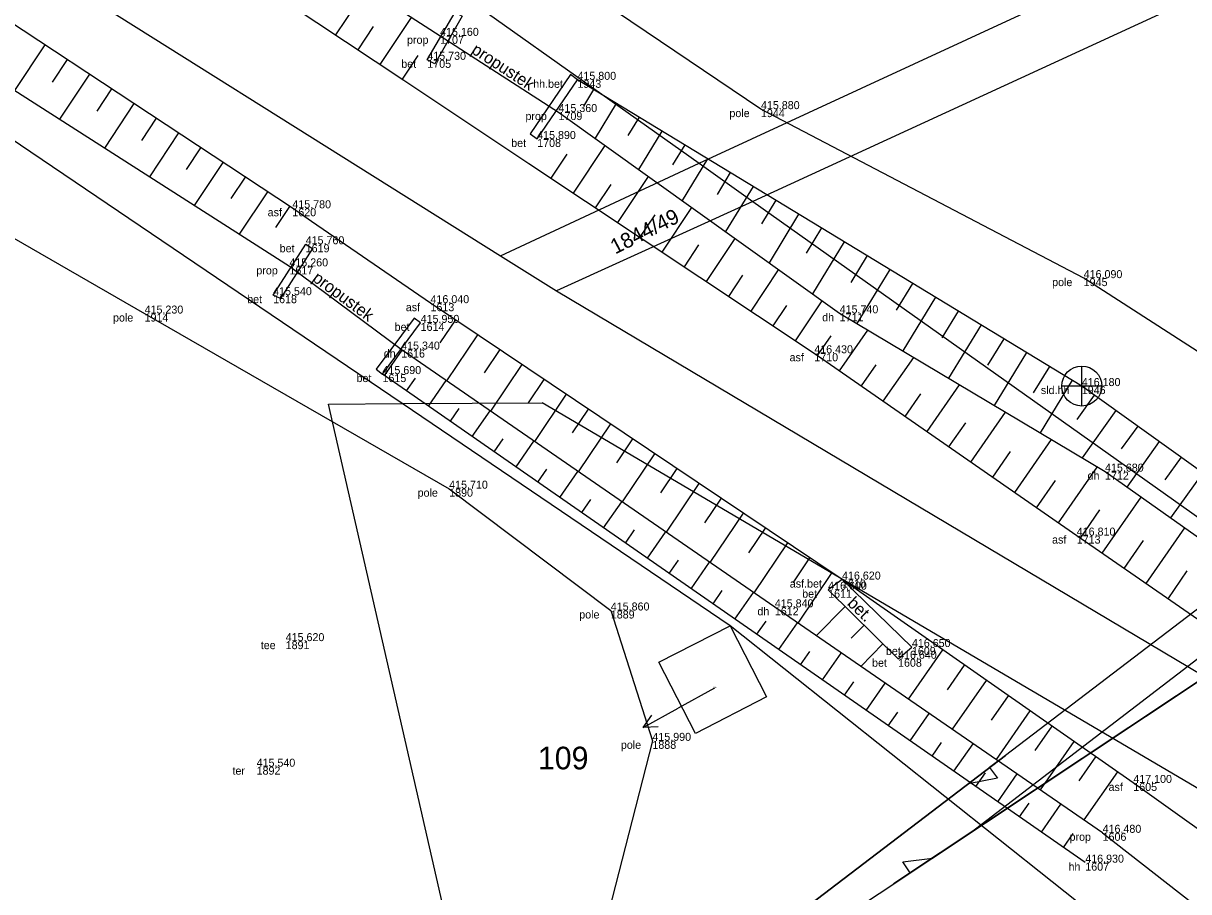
# Model space of a CAD drawing. Extents: x -747792 to -745414, y -1093712 to -1091463.
# Drawn here: x -746827.19 to -746783.49, y -1092384.49 to -1092351.91 of the extents above; entities that cross this region are included whole.
import ezdxf

# ---------------------------------------------------------------- set-up
doc = ezdxf.new("R2010")
doc.units = 0
for name, color, linetype in [('Doplňkové značky', 7, 'Continuous'), ('Hladina', 7, 'Continuous'), ('Koleje_dopravní prvky', 7, 'Continuous'), ('Nivelační značky_hrany', 7, 'Continuous'), ('Pracovní_bod JDTM STC_VC - výška', 7, 'Continuous'), ('Pracovní_bod PPBP', 7, 'Continuous'), ('Pracovní_bod ZPBP', 7, 'Continuous'), ('Pracovní_bod ZPBP - číslo', 7, 'Continuous'), ('Rozhraní ploch', 7, 'Continuous'), ('Stromy_porost', 7, 'Continuous'), ('Výškopis', 7, 'Continuous'), ('Značky IS', 7, 'Continuous'), ('Čísla popisná_parcelní', 7, 'Continuous')]:
    doc.layers.add(name, color=color, linetype=linetype)

msp = doc.modelspace()

# ---------------------------------------------------------------- linework, layer by layer
at = {"layer": 'Doplňkové značky'}
for points in [[(-746801.27, -1092376.85), (-746802.63, -1092377.6)], [(-746803.944, -1092378.324), (-746802.63, -1092377.6)], [(-746803.385, -1092378.302), (-746803.944, -1092378.324), (-746803.626, -1092377.864)]]:
    msp.add_lwpolyline(points, dxfattribs=at)
at = {"layer": 'Hladina'}
for p, q in [((-746811.56, -1092352.38), (-746811.56, -1092352.38)), ((-746812.04, -1092353.28), (-746812.04, -1092353.28)), ((-746806.41, -1092354.03), (-746806.41, -1092354.03)), ((-746807.12, -1092355.24), (-746807.12, -1092355.24)), ((-746799.53, -1092355.13), (-746799.53, -1092355.13)), ((-746807.92, -1092356.25), (-746807.92, -1092356.25)), ((-746817.1, -1092358.85), (-746817.1, -1092358.85)), ((-746816.6, -1092360.2), (-746816.6, -1092360.2)), ((-746817.21, -1092361.03), (-746817.21, -1092361.03)), ((-746787.43, -1092361.47), (-746787.43, -1092361.47)), ((-746817.82, -1092362.11), (-746817.82, -1092362.11)), ((-746811.92, -1092362.41), (-746811.92, -1092362.41)), ((-746822.64, -1092362.8), (-746822.64, -1092362.8)), ((-746796.58, -1092362.79), (-746796.58, -1092362.79)), ((-746812.29, -1092363.15), (-746812.29, -1092363.15)), ((-746813.02, -1092364.15), (-746813.02, -1092364.15)), ((-746797.53, -1092364.29), (-746797.53, -1092364.29)), ((-746813.72, -1092365.07), (-746813.72, -1092365.07)), ((-746787.5, -1092365.52), (-746787.5, -1092365.52)), ((-746786.63, -1092368.73), (-746786.63, -1092368.73)), ((-746811.22, -1092369.37), (-746811.22, -1092369.37)), ((-746787.69, -1092371.13), (-746787.69, -1092371.13)), ((-746796.49, -1092372.78), (-746796.49, -1092372.78)), ((-746797.01, -1092373.16), (-746797.01, -1092373.16)), ((-746799.01, -1092373.82), (-746799.01, -1092373.82)), ((-746805.16, -1092373.94), (-746805.16, -1092373.94)), ((-746817.35, -1092375.09), (-746817.35, -1092375.09)), ((-746793.87, -1092375.31), (-746793.87, -1092375.31)), ((-746794.39, -1092375.75), (-746794.39, -1092375.75)), ((-746803.6, -1092378.83), (-746803.6, -1092378.83)), ((-746818.44, -1092379.8), (-746818.44, -1092379.8)), ((-746785.57, -1092380.41), (-746785.57, -1092380.41)), ((-746786.72, -1092382.28), (-746786.72, -1092382.28)), ((-746787.37, -1092383.4), (-746787.37, -1092383.4))]:
    msp.add_line(p, q, dxfattribs=at)
at = {"layer": 'Nivelační značky_hrany'}
for points in [[(-746816.378, -1092359.346), (-746817.1, -1092358.85), (-746833.74, -1092347.85), (-746852.12, -1092335.65), (-746868.14, -1092324.85), (-746875.06, -1092319.76), (-746884.36, -1092312.88), (-746888.58, -1092309.74), (-746904.34, -1092297.28), (-746918.62, -1092285.83), (-746930.682, -1092276.083)], [(-746887.66, -1092302.09), (-746880.53, -1092307.62), (-746872.41, -1092313.76), (-746861.83, -1092321.34), (-746850.87, -1092329.15), (-746834.21, -1092340.08), (-746822.74, -1092347.51), (-746812.918, -1092354.047)], [(-746812.04, -1092353.28), (-746810.99, -1092351.49), (-746810.73, -1092351.64), (-746811.762, -1092353.434), (-746812.04, -1092353.28)], [(-746812.916, -1092354.049), (-746808.229, -1092357.169)], [(-746807.92, -1092356.25), (-746806.41, -1092354.03), (-746806.67, -1092353.83), (-746808.188, -1092356.058), (-746807.92, -1092356.25)], [(-746808.227, -1092357.17), (-746797.53, -1092364.29), (-746787.69, -1092371.13), (-746776.62, -1092378.78), (-746765.54, -1092386.79), (-746755.3, -1092394.62), (-746745.57, -1092402.66), (-746737.91, -1092409.79), (-746728.85, -1092419.26), (-746722.7, -1092426.86), (-746714.67, -1092437.95), (-746707.62, -1092449.35), (-746700.44, -1092461.3), (-746693.84, -1092472.82), (-746684.01, -1092490.2), (-746680.08, -1092497.02)], [(-746774.902, -1092388.005), (-746776.84, -1092386.65), (-746785.57, -1092380.41), (-746796.49, -1092372.78), (-746811.92, -1092362.41), (-746816.377, -1092359.347)], [(-746817.82, -1092362.11), (-746816.6, -1092360.2), (-746816.347, -1092360.362), (-746817.548, -1092362.236), (-746817.82, -1092362.11)], [(-746813.72, -1092365.07), (-746812.29, -1092363.15), (-746812.53, -1092362.97), (-746813.962, -1092364.883), (-746813.72, -1092365.07)], [(-746796.49, -1092372.78), (-746797.01, -1092373.16), (-746794.39, -1092375.75), (-746793.87, -1092375.31), (-746796.49, -1092372.78)]]:
    msp.add_lwpolyline(points, dxfattribs=at)
at = {"layer": 'Pracovní_bod JDTM STC_VC - výška'}
for points in [[(-746938.71, -1092286.05), (-746933.44, -1092286.22), (-746925.65, -1092289.67), (-746915.11, -1092297.76), (-746902.08, -1092308.43), (-746888.12, -1092318.25), (-746871.41, -1092330.26), (-746860.11, -1092339.08), (-746848.88, -1092347.29), (-746835.4, -1092355.44), (-746822.64, -1092362.8), (-746811.22, -1092369.37), (-746805.16, -1092373.94), (-746803.6, -1092378.83), (-746805.87, -1092387.71)], [(-746666.48, -1092509.53), (-746671.18, -1092501.38), (-746679.28, -1092488.1), (-746683.01, -1092480.66), (-746691.02, -1092465.89), (-746695.91, -1092457.38), (-746697.67, -1092451.5), (-746700.29, -1092444.13), (-746704.56, -1092439.88), (-746720.11, -1092421.5), (-746727.2, -1092412.89), (-746738.25, -1092401.15), (-746749.37, -1092389.72), (-746764.79, -1092376.86), (-746776.64, -1092368.43), (-746787.43, -1092361.47), (-746799.53, -1092355.13), (-746817.34, -1092343.1), (-746824.75, -1092337.86), (-746838.2, -1092329.38), (-746851.64, -1092319.28)]]:
    msp.add_lwpolyline(points, dxfattribs=at)
at = {"layer": 'Pracovní_bod PPBP'}
for points in [[(-746817.21, -1092361.03), (-746835.12, -1092349.56), (-746853.28, -1092337.31), (-746869.22, -1092326.11), (-746875.84, -1092321.59), (-746885.39, -1092314.53), (-746906.03, -1092297.92), (-746919.3, -1092287.66), (-746931.74, -1092277.72)], [(-746886.98, -1092300.01), (-746879.5, -1092306.35), (-746871.83, -1092312.38), (-746860.78, -1092320.38), (-746850.53, -1092327.24), (-746833.2, -1092338.57), (-746822.17, -1092345.53), (-746811.56, -1092352.38)], [(-746815.471, -1092352.348), (-746814.31, -1092350.604)], [(-746814.638, -1092352.902), (-746814.054, -1092352.025)], [(-746813.806, -1092353.457), (-746812.63, -1092351.689)], [(-746826.379, -1092352.716), (-746827.513, -1092354.432)], [(-746825.545, -1092353.267), (-746826.108, -1092354.119)], [(-746812.974, -1092354.011), (-746812.382, -1092353.121)], [(-746824.711, -1092353.819), (-746825.829, -1092355.51)], [(-746676.31, -1092494.93), (-746679.28, -1092488.1), (-746684.61, -1092481.19), (-746692.58, -1092466.75), (-746703.9, -1092446.01), (-746716.46, -1092426.76), (-746727.325, -1092413.107), (-746739.95, -1092401.9), (-746747.98, -1092394.64), (-746752.03, -1092391.71), (-746753.83, -1092389.76), (-746758.64, -1092386.23), (-746765.82, -1092381.07), (-746787.5, -1092365.52), (-746806.41, -1092354.03)], [(-746823.877, -1092354.37), (-746824.432, -1092355.21)], [(-746805.808, -1092354.396), (-746806.185, -1092355.017)], [(-746823.042, -1092354.922), (-746824.145, -1092356.589)], [(-746804.953, -1092354.915), (-746805.748, -1092356.223)], [(-746822.208, -1092355.473), (-746822.755, -1092356.301)], [(-746807.12, -1092355.24), (-746796.58, -1092362.79), (-746786.63, -1092368.73), (-746775.02, -1092376.93), (-746764.6, -1092384.11), (-746753.89, -1092392.74), (-746744.6, -1092400.27), (-746734.99, -1092408.91), (-746726.93, -1092417.05), (-746720.19, -1092425.45), (-746712.76, -1092435.88), (-746705, -1092448.32), (-746698.55, -1092460.04), (-746691.76, -1092472.37), (-746682.53, -1092488.74), (-746678.42, -1092495.91)], [(-746804.099, -1092355.434), (-746804.516, -1092356.121)], [(-746803.244, -1092355.954), (-746804.117, -1092357.391)], [(-746821.374, -1092356.025), (-746822.46, -1092357.668)], [(-746820.54, -1092356.576), (-746821.079, -1092357.392)], [(-746807.395, -1092357.724), (-746806.791, -1092356.816)], [(-746806.563, -1092358.278), (-746805.373, -1092356.491)], [(-746802.389, -1092356.473), (-746802.846, -1092357.224)], [(-746819.706, -1092357.128), (-746820.776, -1092358.746)], [(-746801.535, -1092356.992), (-746802.487, -1092358.559)], [(-746818.871, -1092357.679), (-746819.402, -1092358.482)], [(-746804.898, -1092359.386), (-746803.746, -1092357.657)], [(-746800.68, -1092357.512), (-746801.176, -1092358.327)], [(-746805.73, -1092358.832), (-746805.145, -1092357.953)], [(-746799.826, -1092358.031), (-746800.856, -1092359.727)], [(-746818.037, -1092358.23), (-746819.091, -1092359.825)], [(-746798.971, -1092358.55), (-746799.506, -1092359.431)], [(-746817.203, -1092358.782), (-746817.726, -1092359.573)], [(-746803.233, -1092360.494), (-746802.12, -1092358.822)], [(-746804.065, -1092359.94), (-746803.499, -1092359.09)], [(-746798.116, -1092359.069), (-746799.226, -1092360.895)], [(-746797.262, -1092359.589), (-746797.836, -1092360.534)], [(-746802.4, -1092361.048), (-746801.853, -1092360.226)], [(-746801.568, -1092361.602), (-746800.493, -1092359.987)], [(-746796.407, -1092360.108), (-746797.595, -1092362.063)], [(-746795.552, -1092360.627), (-746796.166, -1092361.637)], [(-746799.903, -1092362.711), (-746798.866, -1092361.153)], [(-746794.698, -1092361.146), (-746795.932, -1092363.177)], [(-746800.735, -1092362.156), (-746800.207, -1092361.363)], [(-746793.843, -1092361.666), (-746794.458, -1092362.678)], [(-746799.07, -1092363.265), (-746798.561, -1092362.5)], [(-746798.238, -1092363.819), (-746797.239, -1092362.318)], [(-746792.989, -1092362.185), (-746794.214, -1092364.202)], [(-746792.134, -1092362.704), (-746792.745, -1092363.71)], [(-746810.986, -1092363.038), (-746811.564, -1092363.897)], [(-746791.279, -1092363.224), (-746792.497, -1092365.227)], [(-746810.156, -1092363.596), (-746811.318, -1092365.325)], [(-746797.407, -1092364.375), (-746796.897, -1092363.641)], [(-746796.586, -1092364.946), (-746795.525, -1092363.42)], [(-746790.425, -1092363.743), (-746791.032, -1092364.741)], [(-746813.639, -1092365.126), (-746812.98, -1092364.178)], [(-746786.72, -1092382.28), (-746799.01, -1092373.82), (-746813.02, -1092364.15)], [(-746809.326, -1092364.153), (-746809.911, -1092365.023)], [(-746789.57, -1092364.262), (-746790.78, -1092366.253)], [(-746808.496, -1092364.711), (-746809.672, -1092366.461)], [(-746795.765, -1092365.517), (-746795.215, -1092364.725)], [(-746794.944, -1092366.088), (-746793.804, -1092364.447)], [(-746787.37, -1092383.4), (-746813.72, -1092365.07)], [(-746788.716, -1092364.781), (-746789.318, -1092365.773)], [(-746812.818, -1092365.697), (-746812.487, -1092365.222)], [(-746811.997, -1092366.268), (-746811.334, -1092365.314)], [(-746807.666, -1092365.269), (-746808.258, -1092366.149)], [(-746793.302, -1092367.229), (-746792.082, -1092365.475)], [(-746787.861, -1092365.301), (-746789.062, -1092367.278)], [(-746806.836, -1092365.827), (-746808.026, -1092367.597)], [(-746794.123, -1092366.658), (-746793.533, -1092365.81)], [(-746787.031, -1092365.857), (-746787.692, -1092366.779)], [(-746811.176, -1092366.839), (-746810.843, -1092366.361)], [(-746810.356, -1092367.41), (-746809.688, -1092366.45)], [(-746806.006, -1092366.385), (-746806.604, -1092367.275)], [(-746786.218, -1092366.439), (-746787.492, -1092368.215)], [(-746792.481, -1092367.8), (-746791.851, -1092366.894)], [(-746791.659, -1092368.371), (-746790.361, -1092366.503)], [(-746805.176, -1092366.942), (-746806.38, -1092368.733)], [(-746785.405, -1092367.022), (-746786.018, -1092367.876)], [(-746809.535, -1092367.982), (-746809.2, -1092367.5)], [(-746808.714, -1092368.553), (-746808.042, -1092367.586)], [(-746804.346, -1092367.5), (-746804.951, -1092368.401)], [(-746790.017, -1092369.512), (-746788.64, -1092367.53)], [(-746784.593, -1092367.605), (-746785.813, -1092369.307)], [(-746803.516, -1092368.058), (-746804.734, -1092369.869)], [(-746790.838, -1092368.941), (-746790.169, -1092367.979)], [(-746783.78, -1092368.188), (-746784.388, -1092369.036)], [(-746807.893, -1092369.124), (-746807.556, -1092368.639)], [(-746802.686, -1092368.616), (-746803.298, -1092369.527)], [(-746788.375, -1092370.654), (-746786.918, -1092368.558)], [(-746807.072, -1092369.695), (-746806.396, -1092368.722)], [(-746789.196, -1092370.083), (-746788.488, -1092369.064)], [(-746782.968, -1092368.771), (-746784.18, -1092370.461)], [(-746801.856, -1092369.174), (-746803.088, -1092371.006)], [(-746806.251, -1092370.266), (-746805.912, -1092369.778)], [(-746805.43, -1092370.837), (-746804.75, -1092369.858)], [(-746801.026, -1092369.731), (-746801.645, -1092370.653)], [(-746786.731, -1092371.793), (-746785.276, -1092369.687)], [(-746800.196, -1092370.289), (-746801.441, -1092372.142)], [(-746787.554, -1092371.224), (-746786.823, -1092370.167)], [(-746785.086, -1092372.93), (-746783.642, -1092370.84)], [(-746804.609, -1092371.408), (-746804.268, -1092370.917)], [(-746803.788, -1092371.979), (-746803.104, -1092370.995)], [(-746799.366, -1092370.847), (-746799.992, -1092371.778)], [(-746798.536, -1092371.405), (-746799.795, -1092373.278)], [(-746785.908, -1092372.361), (-746785.184, -1092371.312)], [(-746802.967, -1092372.55), (-746802.624, -1092372.056)], [(-746802.146, -1092373.121), (-746801.458, -1092372.131)], [(-746797.706, -1092371.963), (-746798.339, -1092372.904)], [(-746796.876, -1092372.52), (-746798.148, -1092374.413)], [(-746784.263, -1092373.498), (-746783.544, -1092372.458)], [(-746801.325, -1092373.692), (-746800.98, -1092373.195)], [(-746800.505, -1092374.263), (-746799.812, -1092373.267)], [(-746796.377, -1092373.786), (-746797.463, -1092374.885)], [(-746799.684, -1092374.834), (-746799.336, -1092374.334)], [(-746798.863, -1092375.405), (-746798.165, -1092374.402)], [(-746795.666, -1092374.489), (-746796.146, -1092374.975)], [(-746794.954, -1092375.192), (-746795.79, -1092376.037)], [(-746798.042, -1092375.976), (-746797.691, -1092375.473)], [(-746797.221, -1092376.547), (-746796.517, -1092375.536)], [(-746792.726, -1092375.421), (-746794.01, -1092377.262)], [(-746791.905, -1092375.993), (-746792.546, -1092376.911)], [(-746796.4, -1092377.118), (-746796.047, -1092376.611)], [(-746795.579, -1092377.689), (-746794.87, -1092376.67)], [(-746791.085, -1092376.564), (-746792.362, -1092378.396)], [(-746790.265, -1092377.136), (-746790.902, -1092378.05)], [(-746794.758, -1092378.261), (-746794.402, -1092377.749)], [(-746793.937, -1092378.832), (-746793.222, -1092377.804)], [(-746789.444, -1092377.708), (-746790.715, -1092379.53)], [(-746788.624, -1092378.28), (-746789.258, -1092379.189)], [(-746793.116, -1092379.403), (-746792.758, -1092378.887)], [(-746792.295, -1092379.974), (-746791.575, -1092378.938)], [(-746787.804, -1092378.852), (-746789.067, -1092380.664)], [(-746786.984, -1092379.424), (-746787.614, -1092380.328)], [(-746786.163, -1092379.996), (-746787.42, -1092381.798)], [(-746791.475, -1092380.545), (-746791.113, -1092380.025)], [(-746790.654, -1092381.116), (-746789.928, -1092380.072)], [(-746789.833, -1092381.687), (-746789.468, -1092381.163)], [(-746789.012, -1092382.258), (-746788.28, -1092381.206)], [(-746788.191, -1092382.829), (-746787.824, -1092382.301)]]:
    msp.add_lwpolyline(points, dxfattribs=at)
at = {"layer": 'Pracovní_bod ZPBP'}
for points in [[(-746811.56, -1092352.38), (-746807.12, -1092355.24)], [(-746813.02, -1092364.15), (-746817.21, -1092361.03)], [(-746786.72, -1092382.28), (-746776.53, -1092390.25)]]:
    msp.add_lwpolyline(points, dxfattribs=at)
at = {"layer": 'Stromy_porost'}
for points in [[(-746863.04, -1092313.75), (-746801.85, -1092357.16)], [(-746879.52, -1092316.53), (-746809.3, -1092360.63)], [(-746812.98, -1092366.18), (-746863.74, -1092331.79)], [(-746801.85, -1092357.16), (-746759.4, -1092337.52)], [(-746758.85, -1092339.71), (-746799.83, -1092358.59)], [(-746809.3, -1092360.63), (-746801.85, -1092357.16)], [(-746801.85, -1092357.16), (-746799.83, -1092358.59)], [(-746799.83, -1092358.59), (-746807.2, -1092361.95)], [(-746799.83, -1092358.59), (-746741.55, -1092399.95)], [(-746809.3, -1092360.63), (-746807.2, -1092361.95)], [(-746807.2, -1092361.95), (-746768.8, -1092384.81)], [(-746815.74, -1092366.2), (-746812.98, -1092366.18)], [(-746809.67, -1092392.83), (-746815.74, -1092366.2)], [(-746812.98, -1092366.18), (-746807.73, -1092366.15)], [(-746800.69, -1092374.51), (-746812.98, -1092366.18)], [(-746771.02, -1092387.76), (-746807.73, -1092366.15)], [(-746803.36, -1092375.88), (-746800.69, -1092374.51)], [(-746800.69, -1092374.51), (-746799.32, -1092377.18)], [(-746786.6, -1092385.72), (-746800.69, -1092374.51)], [(-746801.99, -1092378.55), (-746803.36, -1092375.88)], [(-746799.32, -1092377.18), (-746801.99, -1092378.55)]]:
    msp.add_lwpolyline(points, dxfattribs=at)
at = {"layer": 'Značky IS'}
for points in [[(-746791.643, -1092382.261), (-746738.84, -1092341.76), (-746766.63, -1092363.075)], [(-746772.427, -1092365.696), (-746811.08, -1092395.19), (-746790.362, -1092379.381)], [(-746811.08, -1092395.19), (-746775.12, -1092371.27), (-746794.557, -1092384.199)], [(-746790.561, -1092379.533), (-746790.959, -1092379.836), (-746790.655, -1092380.234), (-746791.754, -1092380.443), (-746792.946, -1092381.353)], [(-746794.349, -1092384.061), (-746793.933, -1092383.784), (-746794.21, -1092383.368), (-746793.1, -1092383.23), (-746791.851, -1092382.399)]]:
    msp.add_lwpolyline(points, dxfattribs=at)
at = {"layer": 'Čísla popisná_parcelní'}
for p, q in [((-746787.501, -1092366.268), (-746787.5, -1092364.773)), ((-746786.748, -1092365.526), (-746788.248, -1092365.521))]:
    msp.add_line(p, q, dxfattribs=at)
msp.add_circle((-746787.5, -1092365.52), 0.75, dxfattribs=at)

# ---------------------------------------------------------------- texts
at = {"layer": 'Doplňkové značky'}
msp.add_text('109', height=0.85, dxfattribs=at).set_placement((-746807.893, -1092379.9))
at = {"layer": 'Koleje_dopravní prvky'}
msp.add_text('1844/49', height=0.57, rotation=26.8144, dxfattribs=at).set_placement((-746804.994, -1092360.589))
msp.add_text('109', height=0.05, dxfattribs=at).set_placement((-746801.318, -1092376.85))
at = {"layer": 'Pracovní_bod ZPBP - číslo'}
for s, rotation, p in [('propustek', 326.8221, (-746810.422, -1092353.005)), ('propustek', 323.5652, (-746816.381, -1092361.549)), ('bet.', 315.8383, (-746796.325, -1092373.704))]:
    msp.add_text(s, height=0.45, rotation=rotation, dxfattribs=at).set_placement(p)
at = {"layer": 'Rozhraní ploch'}
for s, p in [(' prop', (-746812.911, -1092352.68)), ('1707', (-746811.56, -1092352.68)), (' bet', (-746813.126, -1092353.58)), ('1705', (-746812.04, -1092353.58)), (' hh.bet', (-746808.181, -1092354.33)), ('1943', (-746806.41, -1092354.33)), (' prop', (-746808.471, -1092355.54)), ('1709', (-746807.12, -1092355.54)), (' pole', (-746800.824, -1092355.43)), ('1944', (-746799.53, -1092355.43)), (' bet', (-746809.006, -1092356.55)), ('1708', (-746807.92, -1092356.55)), (' asf', (-746818.137, -1092359.15)), ('1620', (-746817.1, -1092359.15)), (' bet', (-746817.686, -1092360.5)), ('1619', (-746816.6, -1092360.5)), (' prop', (-746818.561, -1092361.33)), ('1617', (-746817.21, -1092361.33)), (' pole', (-746788.724, -1092361.77)), ('1945', (-746787.43, -1092361.77)), (' bet', (-746818.906, -1092362.41)), ('1618', (-746817.82, -1092362.41)), (' asf', (-746812.957, -1092362.71)), ('1613', (-746811.92, -1092362.71)), (' pole', (-746823.934, -1092363.1)), ('1914', (-746822.64, -1092363.1)), (' dh', (-746797.345, -1092363.09)), ('1711', (-746796.58, -1092363.09)), (' bet', (-746813.376, -1092363.45)), ('1614', (-746812.29, -1092363.45)), (' dh', (-746813.785, -1092364.45)), ('1616', (-746813.02, -1092364.45)), (' asf', (-746798.567, -1092364.59)), ('1710', (-746797.53, -1092364.59)), (' bet', (-746814.806, -1092365.37)), ('1615', (-746813.72, -1092365.37)), (' sld.hh', (-746789.146, -1092365.82)), ('1946', (-746787.5, -1092365.82)), (' dh', (-746787.395, -1092369.03)), ('1712', (-746786.63, -1092369.03)), (' pole', (-746812.514, -1092369.67)), ('1890', (-746811.22, -1092369.67)), (' asf', (-746788.727, -1092371.43)), ('1713', (-746787.69, -1092371.43)), (' asf.bet', (-746798.559, -1092373.08)), ('1610', (-746796.49, -1092373.08)), (' bet', (-746798.096, -1092373.46)), ('1611', (-746797.01, -1092373.46)), (' dh', (-746799.775, -1092374.12)), ('1612', (-746799.01, -1092374.12)), (' pole', (-746806.454, -1092374.24)), ('1889', (-746805.16, -1092374.24)), (' tee', (-746818.396, -1092375.39)), ('1891', (-746817.35, -1092375.39)), (' bet', (-746794.956, -1092375.61)), ('1609', (-746793.87, -1092375.61)), (' bet', (-746795.476, -1092376.05)), ('1608', (-746794.39, -1092376.05)), (' pole', (-746804.894, -1092379.13)), ('1888', (-746803.6, -1092379.13)), (' ter', (-746819.456, -1092380.1)), ('1892', (-746818.44, -1092380.1)), (' asf', (-746786.607, -1092380.71)), ('1605', (-746785.57, -1092380.71)), (' prop', (-746788.071, -1092382.58)), ('1606', (-746786.72, -1092382.58)), (' hh', (-746788.109, -1092383.7)), ('1607', (-746787.37, -1092383.7))]:
    msp.add_text(s, height=0.3, dxfattribs=at).set_placement(p)
at = {"layer": 'Výškopis'}
for s, p in [('415,160', (-746811.56, -1092352.38)), ('415,730', (-746812.04, -1092353.28)), ('415,800', (-746806.41, -1092354.03)), ('415,360', (-746807.12, -1092355.24)), ('415,880', (-746799.53, -1092355.13)), ('415,890', (-746807.92, -1092356.25)), ('415,780', (-746817.1, -1092358.85)), ('415,760', (-746816.6, -1092360.2)), ('415,260', (-746817.21, -1092361.03)), ('416,090', (-746787.43, -1092361.47)), ('415,540', (-746817.82, -1092362.11)), ('415,230', (-746822.64, -1092362.8)), ('416,040', (-746811.92, -1092362.41)), ('415,740', (-746796.58, -1092362.79)), ('415,950', (-746812.29, -1092363.15)), ('415,340', (-746813.02, -1092364.15)), ('416,430', (-746797.53, -1092364.29)), ('415,690', (-746813.72, -1092365.07)), ('416,180', (-746787.5, -1092365.52)), ('415,680', (-746786.63, -1092368.73)), ('415,710', (-746811.22, -1092369.37)), ('416,810', (-746787.69, -1092371.13)), ('416,620', (-746796.49, -1092372.78)), ('416,600', (-746797.01, -1092373.16)), ('415,860', (-746805.16, -1092373.94)), ('415,840', (-746799.01, -1092373.82)), ('415,620', (-746817.35, -1092375.09)), ('416,650', (-746793.87, -1092375.31)), ('416,640', (-746794.39, -1092375.75)), ('415,990', (-746803.6, -1092378.83)), ('415,540', (-746818.44, -1092379.8)), ('417,100', (-746785.57, -1092380.41)), ('416,480', (-746786.72, -1092382.28)), ('416,930', (-746787.37, -1092383.4))]:
    msp.add_text(s, height=0.3, dxfattribs=at).set_placement(p)

doc.saveas('drawing.dxf')
